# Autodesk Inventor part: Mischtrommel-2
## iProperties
Shininess: 64.0
Length Units: 11269
Angle Units: 11279
Time Units: 11290
Mass Units: 11283
Length Display Precision: 3
Angle Display Precision: 2
Compacted: True
Part Number: Mischtrommel-2
Document SubType Name: Modeling
Created: 2005-09
Material: S 235 JR
Designer: Frank
Manufacturer: Standard
Standards Organization: Custom
Density: 0.0
Volumn: 0.0
Area: 0.0
PropertySet Name: Model Information
Control State: 0
Master: False
Checked Out: False
Author: Frank
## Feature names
1. Extrusion1
